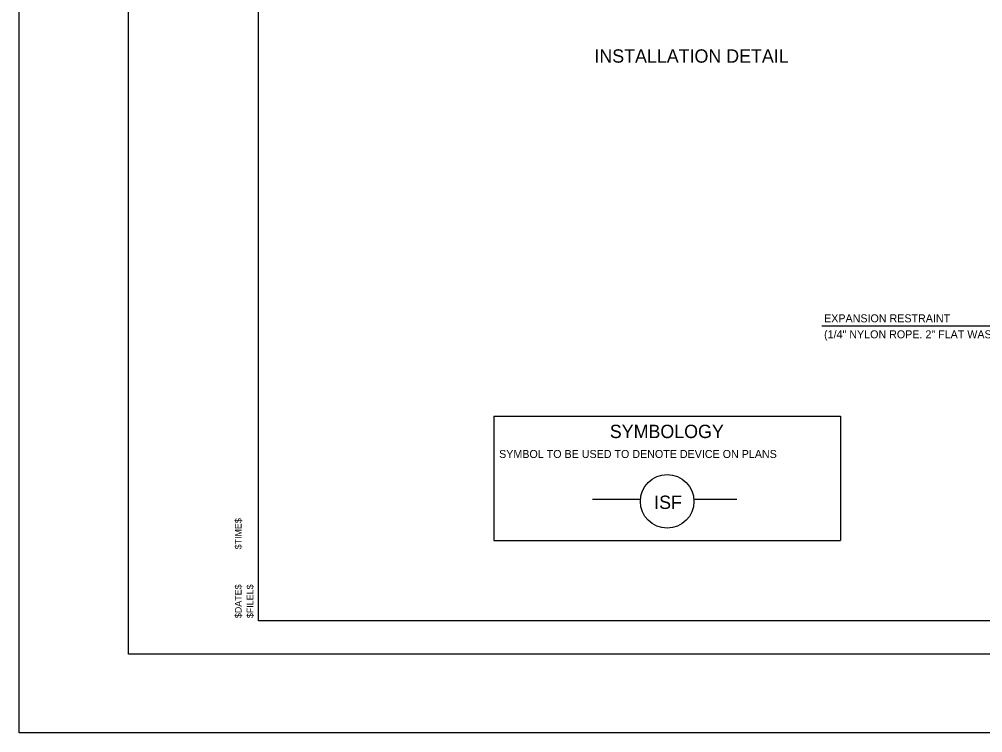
# Model space of a CAD drawing. Extents: x -120.7 to -50.3, y -20.2 to 3.8.
# Drawn here: x -86.26 to -71.81, y -20.24 to -9.55 of the extents above; entities that cross this region are included whole.
import ezdxf

# ---------------------------------------------------------------- set-up
doc = ezdxf.new("R2010")
doc.units = 0
for name, color, linetype in [('PR_Dimensions', 7, 'Continuous'), ('SHT_Plot_Shape_Full', 7, 'Continuous'), ('SHT_Plot_Shape_Half', 7, 'Continuous'), ('SHT_Plot_Stamp', 7, 'Continuous'), ('SHT_Sheet_Border', 7, 'Continuous'), ('TYP_Typical_Section_Linework', 7, 'Continuous'), ('TYP_Typical_Section_Txt', 7, 'Continuous')]:
    doc.layers.add(name, color=color, linetype=linetype)

msp = doc.modelspace()

# ---------------------------------------------------------------- linework, layer by layer
at = {"layer": 'PR_Dimensions'}
msp.add_line((-70.434, -14.151), (-74.224, -14.151), dxfattribs=at)
at = {"layer": 'SHT_Plot_Shape_Full'}
msp.add_lwpolyline([(-86.259, 3.759), (-50.259, 3.759), (-50.259, -20.241), (-86.259, -20.241)], close=True, dxfattribs=at)
at = {"layer": 'SHT_Plot_Shape_Half'}
msp.add_lwpolyline([(-84.622, 2.934), (-50.622, 2.934), (-50.622, -19.066), (-84.622, -19.066)], close=True, dxfattribs=at)
at = {"layer": 'SHT_Sheet_Border'}
msp.add_lwpolyline([(-51.172, -18.566), (-82.672, -18.566), (-82.672, 2.434), (-51.172, 2.434)], close=True, dxfattribs=at)
at = {"layer": 'TYP_Typical_Section_Linework'}
for p, q in [((-79.144, -15.497), (-79.144, -17.359)), ((-79.144, -15.497), (-73.944, -15.497)), ((-73.944, -15.497), (-73.944, -17.359)), ((-77.666, -16.74), (-76.945, -16.74)), ((-76.143, -16.74), (-75.497, -16.74)), ((-79.144, -17.359), (-73.944, -17.359))]:
    msp.add_line(p, q, dxfattribs=at)
msp.add_circle((-76.544, -16.774), 0.402, dxfattribs=at)

# ---------------------------------------------------------------- texts
at = {"layer": 'SHT_Plot_Stamp'}
for s, p in [('$TIME$', (-82.926, -17.494)), ('$DATE$', (-82.926, -18.524)), ('$FILEL$', (-82.749, -18.524))]:
    msp.add_text(s, height=0.1, rotation=90, dxfattribs=at).set_placement(p)
at = {"layer": 'TYP_Typical_Section_Linework'}
msp.add_text('ISF', height=0.2, dxfattribs=at).set_placement((-76.739, -16.888))
at = {"layer": 'TYP_Typical_Section_Txt'}
for s, height, p in [('INSTALLATION DETAIL', 0.2, (-77.635, -10.2)), ('EXPANSION RESTRAINT', 0.12, (-74.191, -14.091)), ('(1/4" NYLON ROPE. 2" FLAT WASHERS)', 0.12, (-74.191, -14.331)), ('SYMBOLOGY', 0.2, (-77.404, -15.826)), ('SYMBOL TO BE USED TO DENOTE DEVICE ON PLANS', 0.12, (-79.064, -16.124))]:
    msp.add_text(s, height=height, dxfattribs=at).set_placement(p)

doc.saveas('drawing.dxf')
